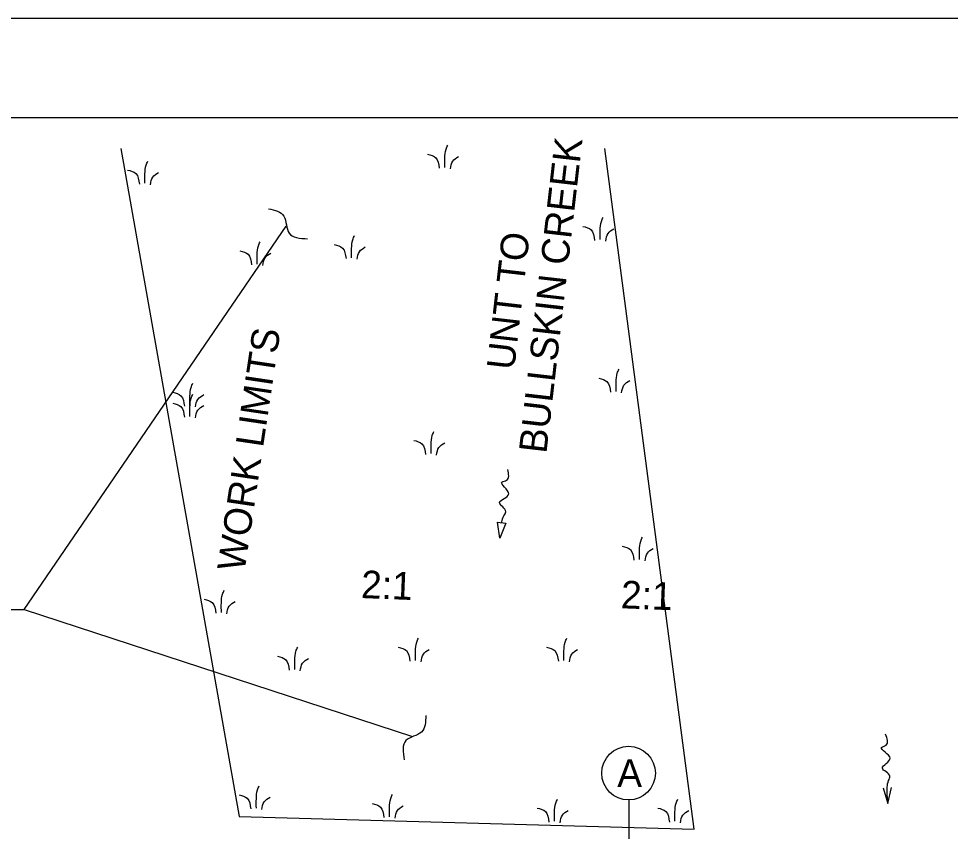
# Model space of a CAD drawing. Extents: x -1270 to 3371, y -118 to 220.
# Drawn here: x 73.78 to 120.85, y 178.92 to 220 of the extents above; entities that cross this region are included whole.
import ezdxf

# ---------------------------------------------------------------- set-up
doc = ezdxf.new("R2010")
doc.units = 0
for name, color, linetype in [('DR_X_Culvert', 7, 'Continuous'), ('GE_P_Alignment', 7, 'Continuous'), ('GE_P_Alignment_100_Distances', 7, 'Continuous'), ('GE_P_Alignment_100_Stations', 7, 'Continuous'), ('MT_P_Transverse_Line', 7, 'Continuous'), ('TX_P_1', 7, 'Continuous'), ('TX_X_1', 7, 'Continuous'), ('TX_X_10', 7, 'Continuous')]:
    doc.layers.add(name, color=color, linetype=linetype)

msp = doc.modelspace()

# ---------------------------------------------------------------- linework, layer by layer
at = {"layer": 'DR_X_Culvert'}
msp.add_lwpolyline([(0, 0), (340, 0), (340, 220), (0, 220)], close=True, dxfattribs=at)
at = {"layer": 'GE_P_Alignment'}
for p, q in [((74.058, 190.135), (87.302, 209.517)), ((72.494, 190.135), (74.058, 190.135)), ((74.058, 190.135), (93.673, 183.718)), ((104.602, 180.507), (104.65, 167.338))]:
    msp.add_line(p, q, dxfattribs=at)
for points in [[(86.406, 210.393), (87.178, 210.014), (87.44, 209.157), (88.381, 208.869)], [(94.352, 184.771), (94.136, 183.939), (93.348, 183.511), (93.254, 182.531)]]:
    msp.add_spline(points, degree=3, dxfattribs=at)
at = {"layer": 'GE_P_Alignment_100_Distances'}
for p, q in [((117.452, 181.121), (117.693, 180.329)), ((117.693, 180.329), (117.881, 181.135))]:
    msp.add_line(p, q, dxfattribs=at)
msp.add_spline([(117.693, 180.329), (117.668, 181.159), (117.732, 181.49), (117.798, 181.701), (117.417, 182.113), (117.813, 182.611), (117.382, 183.157), (117.602, 183.278), (117.578, 183.827)], degree=3, dxfattribs=at)
at = {"layer": 'GE_P_Alignment_100_Stations'}
for p, q in [((98.089, 193.73), (97.968, 194.549)), ((97.968, 194.549), (98.394, 194.5)), ((98.394, 194.5), (98.089, 193.73))]:
    msp.add_line(p, q, dxfattribs=at)
msp.add_spline([(98.183, 194.523), (98.187, 194.555), (98.299, 194.873), (98.395, 195.072), (98.078, 195.535), (98.543, 195.97), (98.197, 196.574), (98.432, 196.661), (98.489, 197.207)], degree=3, dxfattribs=at)
at = {"layer": 'MT_P_Transverse_Line'}
msp.add_lwpolyline([(78.938, 213.442), (84.917, 179.664), (107.908, 179.021), (103.404, 213.442)], dxfattribs=at)
at = {"layer": 'TX_P_1'}
msp.add_circle((104.597, 181.861), 1.355, dxfattribs=at)
at = {"layer": 'TX_X_1'}
msp.add_lwpolyline([(15, 215), (335, 215), (335, 5), (15, 5)], close=True, dxfattribs=at)
at = {"layer": 'TX_X_10'}
for points in [[(95.313, 212.478), (95.313, 212.951), (95.373, 213.395), (95.461, 213.603)], [(80.161, 211.677), (80.161, 212.151), (80.22, 212.595), (80.308, 212.802)], [(94.44, 213.148), (94.854, 212.971), (95.032, 212.438)], [(95.591, 212.406), (95.709, 212.79), (96.004, 213.028)], [(79.287, 212.347), (79.701, 212.171), (79.879, 211.637)], [(80.438, 211.606), (80.556, 211.99), (80.851, 212.227)], [(103.162, 208.829), (103.162, 209.303), (103.221, 209.747), (103.31, 209.954)], [(102.289, 209.499), (102.703, 209.323), (102.881, 208.789)], [(90.603, 207.906), (90.603, 208.379), (90.662, 208.823), (90.75, 209.031)], [(103.44, 208.758), (103.558, 209.142), (103.853, 209.379)], [(85.833, 207.596), (85.833, 208.07), (85.892, 208.514), (85.981, 208.721)], [(89.729, 208.576), (90.144, 208.399), (90.321, 207.866)], [(84.96, 208.266), (85.374, 208.09), (85.551, 207.556)], [(86.111, 207.525), (86.229, 207.909), (86.524, 208.146)], [(90.88, 207.834), (90.999, 208.218), (91.294, 208.456)], [(103.964, 201.157), (103.964, 201.631), (104.023, 202.075), (104.112, 202.282)], [(82.437, 200.442), (82.437, 200.915), (82.497, 201.359), (82.585, 201.567)], [(103.091, 201.827), (103.505, 201.651), (103.682, 201.117)], [(104.242, 201.086), (104.36, 201.47), (104.655, 201.707)], [(81.564, 201.112), (81.978, 200.935), (82.156, 200.402)], [(82.437, 199.892), (82.437, 200.365), (82.497, 200.809), (82.585, 201.017)], [(81.564, 200.562), (81.978, 200.385), (82.156, 199.852)], [(82.715, 200.37), (82.833, 200.754), (83.128, 200.992)], [(82.715, 199.82), (82.833, 200.204), (83.128, 200.442)], [(94.617, 198.011), (94.617, 198.484), (94.676, 198.928), (94.764, 199.136)], [(93.743, 198.681), (94.157, 198.504), (94.335, 197.971)], [(94.894, 197.939), (95.012, 198.323), (95.307, 198.561)], [(105.15, 192.666), (105.15, 193.139), (105.209, 193.583), (105.298, 193.791)], [(104.277, 193.336), (104.691, 193.159), (104.869, 192.626)], [(105.428, 192.594), (105.546, 192.978), (105.841, 193.216)], [(83.149, 190.657), (83.563, 190.48), (83.741, 189.947)], [(84.022, 189.987), (84.022, 190.46), (84.082, 190.904), (84.17, 191.112)], [(84.3, 189.915), (84.418, 190.299), (84.713, 190.537)], [(93.832, 187.56), (93.832, 188.034), (93.891, 188.478), (93.979, 188.685)], [(101.329, 187.56), (101.329, 188.034), (101.389, 188.478), (101.477, 188.685)], [(87.73, 187.105), (87.73, 187.579), (87.789, 188.023), (87.877, 188.23)], [(92.958, 188.23), (93.372, 188.054), (93.55, 187.52)], [(94.109, 187.489), (94.227, 187.873), (94.522, 188.11)], [(100.456, 188.23), (100.87, 188.054), (101.048, 187.52)], [(101.607, 187.489), (101.725, 187.873), (102.02, 188.11)], [(86.856, 187.775), (87.27, 187.599), (87.448, 187.065)], [(88.007, 187.034), (88.125, 187.418), (88.42, 187.655)], [(85.789, 180.096), (85.789, 180.569), (85.848, 181.013), (85.937, 181.221)], [(92.519, 179.654), (92.519, 180.127), (92.578, 180.571), (92.666, 180.779)], [(84.916, 180.766), (85.33, 180.589), (85.507, 180.056)], [(86.067, 180.024), (86.185, 180.408), (86.48, 180.646)], [(91.645, 180.324), (92.059, 180.147), (92.237, 179.614)], [(100.856, 179.425), (100.856, 179.899), (100.915, 180.343), (101.004, 180.55)], [(106.941, 179.425), (106.941, 179.899), (107, 180.343), (107.088, 180.55)], [(92.796, 179.582), (92.914, 179.966), (93.209, 180.204)], [(99.983, 180.095), (100.397, 179.919), (100.574, 179.385)], [(101.134, 179.354), (101.252, 179.738), (101.547, 179.975)], [(106.067, 180.095), (106.482, 179.919), (106.659, 179.385)], [(107.218, 179.354), (107.337, 179.738), (107.632, 179.975)]]:
    msp.add_spline(points, degree=3, dxfattribs=at)

# ---------------------------------------------------------------- texts
at = {"layer": 'GE_P_Alignment'}
for s, p in [('BULLSKIN CREEK', (100.441, 197.984)), ('UNT TO', (98.813, 202.201))]:
    msp.add_text(s, height=1.4, rotation=83.4366, dxfattribs=at).set_placement(p)
at = {"layer": 'TX_P_1'}
for s, rotation, p in [('WORK LIMITS', 81.5382, (85.191, 192.009)), ('2:1', 357.7502, (91.061, 190.712)), ('2:1', 357.7502, (104.19, 190.196))]:
    msp.add_text(s, height=1.4, rotation=rotation, dxfattribs=at).set_placement(p)
msp.add_text('A', height=1.4, dxfattribs=at).set_placement((104.025, 181.161))

doc.saveas('drawing.dxf')
